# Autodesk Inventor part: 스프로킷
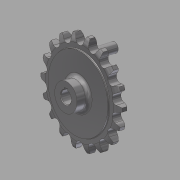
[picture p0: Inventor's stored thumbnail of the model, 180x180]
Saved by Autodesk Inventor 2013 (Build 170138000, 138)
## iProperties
Created: 2016-03
Part Number: 스프로킷
Material: 강철, 탄소
Document SubType Name: Modeling
Designer: mduedu
Density: 7.87 g/cm^3
Mass: 309.165 g
Surface Area: 126.546 cm^2
Volume: 39.2839 cm^3
Author: mduedu
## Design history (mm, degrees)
sketch "스케치1"
  geometry: L1 (0, 5)-(29.5, 5); L2 (29.5, 5)-(29.5, 4.1); L3 (30, 3.6)-(33.625, 3.6); L4 (40, 2)-(40, 0); L5 (40, 0)-(0, 0); L6 (0, 0)-(0, 5); L7 (0, -5)-(29.5, -5); L8 (29.5, -5)-(29.5, -4.1); L9 (30, -3.6)-(33.625, -3.6); L10 (40, -2)-(40, 0); L11 (0, 0)-(0, -5); A1 r 13.5 centre (33.625, -9.9) between (40, 2) and (33.625, 3.6); A2 r 13.5 centre (33.625, 9.9) between (33.625, -3.6) and (40, -2); A3 r 0.5 centre (30, 4.1) between (29.5, 4.1) and (30, 3.6); A4 r 0.5 centre (30, -4.1) between (30, -3.6) and (29.5, -4.1); 2 further points
  constraints: 22 end point, 8 point on circle, 6 symmetric about line, 5 tangent, 4 centre point, 4 parallel, 4 point on line, 1 equal radius, 1 horizontal, 1 perpendicular, 1 other
  dimensions: "d0" = 80 diameter of L4 L6; "d2" = 59 diameter of L2 L6; "d3" = 1.6 vertical distance of L4.start L3.end; "d4" = 3.6 distance from line of L4.end L3; "d5" = 5 distance between parallel lines of L5 L1; "d6" = 13.5 radius of A1; "d15" = 0.5 radius of A3
revolve "회전1" sketch "스케치1" stored, may be unused: angle "d7" = 90 deg
sketch "스케치2" dims "d8" = 65.2, "d11" = 80
  geometry: L1 (0, 0)-(0, 32.6); A1 r 36.57 centre (0, 0) between (-16.231, 32.771) and (0, 36.57); A2 r 3.97 centre (0, 36.57) between (-3.866, 35.665) and (0, 32.6); A3 r 12.7 centre (-16.231, 32.771) between (-3.866, 35.665) and (-5.534, 39.615); A4 r 12.7 centre (16.231, 32.771) between (5.534, 39.615) and (3.866, 35.665); A5 r 3.97 centre (0, 36.57) between (0, 32.6) and (3.866, 35.665); A6 r 40 centre (0, 0) between (5.534, 39.615) and (-5.534, 39.615); 2 further points
  constraints: 12 point on circle, 6 centre point, 4 coincident, 3 symmetric about line, 2 end point, 1 point on line, 1 tangent, 1 vertical, 1 vertical alignment, 7 other
  dimensions: "d10" = 73.14 diameter of A1; "d12" = 12.7 radius of A3
extrude "돌출1" cut sketch "스케치2" stored distance "d13" = 10; taper "d14" = 0 deg
sketch "스케치3"
  geometry: C1 r 11 at (0, 0); 1 further point
  constraints: 1 centre point, 1 coincident
  dimensions: "d19" = 22 diameter of C1
extrude "돌출2" join sketch "스케치3" distance "d20" = 10; taper "d21" = 0 deg
fillet "모깎기1" dims "d22" = 3
sketch "스케치4"
  geometry: L1 (-1.5, 0)-(1.5, 0); L2 (1.5, 0)-(1.5, 6.4); L3 (1.5, 6.4)-(-1.5, 6.4); L4 (-1.5, 6.4)-(-1.5, 0); C1 r 5 at (0, 0); 2 further points
  constraints: 8 end point, 2 coincident, 2 parallel, 1 centre point, 1 horizontal, 1 midpoint, 1 perpendicular
  dimensions: "d23" = 10 diameter of C1; "d25" = 3 distance of L2.end L3.end; "d26" = 6.4 distance of L1.end L2.end
extrude "돌출3" cut sketch "스케치4" stored distance "d27" = 8; taper "d28" = 0 deg
chamfer "모따기1" distance "d29" = 0.5; stored, may be unused: second distance "d30" = 2, angle "d31" = 45 deg
sketch "스케치5" dims "d33" = 48
  geometry: C1 r 4 at (0, 24); 2 further points
  constraints: 2 vertical alignment, 1 centre point, 1 coincident, 2 other
  dimensions: "d32" = 8 diameter of C1
extrude "돌출4" join sketch "스케치5" distance "d34" = 20; taper "d35" = 0 deg
fillet "모깎기2" dims "d36" = 1
hole "구멍1" diameter "d39" = 3.242; stored, may be unused: countersink angle "d43" = 90 deg, drill point angle "d45" = 118 deg; dims "d40" = 8, "d41" = 4, "d42" = 2, "d44" = 10, "d46" = 10, "d47" = 10
node "솔리드1"
pattern_circular "원형 패턴1" dims angle "d17" = 360 deg
